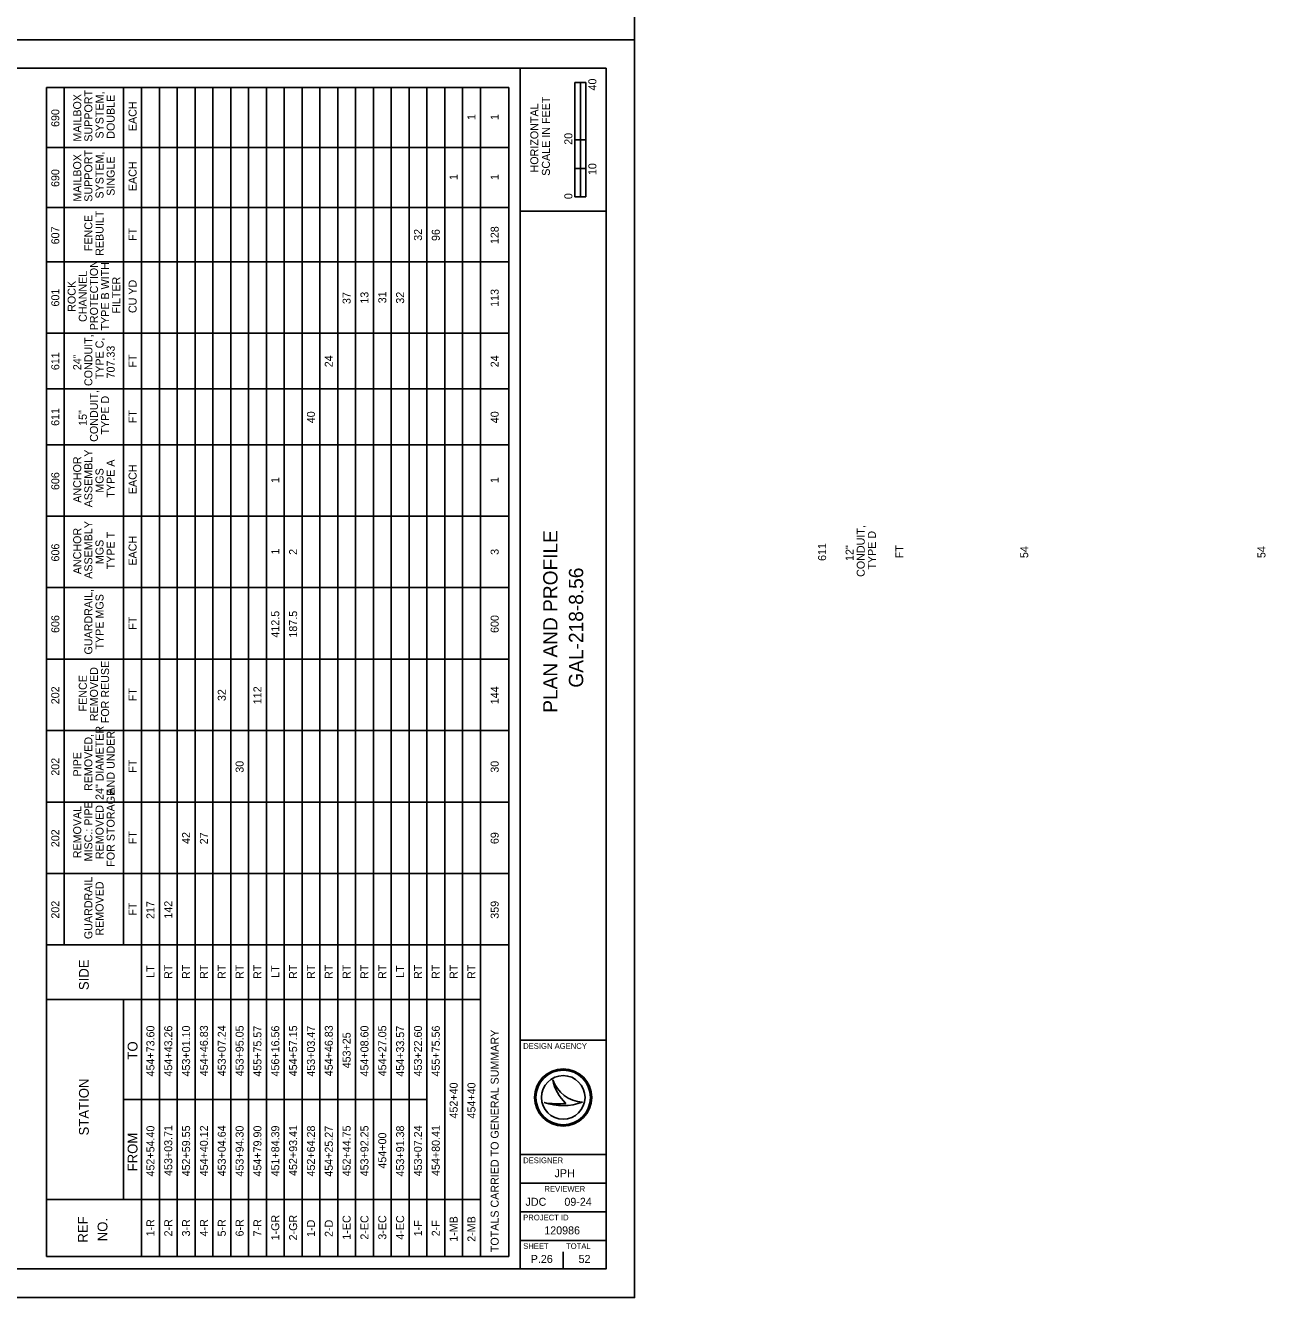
# Model space of a CAD drawing. Extents: x 0 to 3369, y -440 to 440.
# Drawn here: x 466.9 to 900.7, y -440 to 5 of the extents above; entities that cross this region are included whole.
import ezdxf

# ---------------------------------------------------------------- set-up
doc = ezdxf.new("R2010")
doc.units = 0
for name, color, linetype in [('DR_X_Culvert', 7, 'Continuous'), ('PF_X_Ground_Line', 7, 'Continuous'), ('PV_P_EOP', 7, 'Continuous'), ('SC_Scratch1', 7, 'Continuous')]:
    doc.layers.add(name, color=color, linetype=linetype)

msp = doc.modelspace()

# ---------------------------------------------------------------- linework, layer by layer
at = {"layer": 'DR_X_Culvert'}
for p, q in [((474.19, -16.67), (474.19, -425.68)), ((636.03, -16.67), (474.19, -16.67)), ((480.43, -16.67), (480.43, -316.67)), ((501.23, -16.67), (501.23, -316.67)), ((507.47, -16.67), (507.47, -425.68)), ((513.71, -16.67), (513.71, -425.68)), ((519.95, -16.67), (519.95, -425.68)), ((526.19, -16.67), (526.19, -425.68)), ((532.43, -16.67), (532.43, -425.68)), ((538.67, -16.67), (538.67, -425.68)), ((544.91, -16.67), (544.91, -425.68)), ((551.15, -16.67), (551.15, -425.68)), ((557.39, -16.67), (557.39, -425.68)), ((563.63, -16.67), (563.63, -425.68)), ((569.87, -16.67), (569.87, -425.68)), ((576.11, -16.67), (576.11, -425.68)), ((582.35, -16.67), (582.35, -425.68)), ((588.59, -16.67), (588.59, -425.68)), ((594.83, -16.67), (594.83, -425.68)), ((601.07, -16.67), (601.07, -425.68)), ((607.31, -16.67), (607.31, -425.68)), ((613.55, -16.67), (613.55, -425.68)), ((619.79, -16.67), (619.79, -425.68)), ((626.03, -16.67), (626.03, -425.68)), ((636.03, -16.67), (636.03, -425.68)), ((659.13, -55), (659.13, -15)), ((662.88, -15), (659.13, -15)), ((659.13, -35), (659.13, -15)), ((659.13, -15), (661, -15)), ((661, -15), (661.02, -15)), ((661.02, -15), (661.02, -35)), ((662.88, -15), (662.88, -55)), ((661.02, -35), (659.13, -35)), ((662.87, -35), (661, -35)), ((661, -35), (661, -45)), ((662.87, -45), (662.87, -35)), ((636.03, -37.67), (474.19, -37.67)), ((661, -45), (659.13, -45)), ((659.13, -45), (659.13, -55)), ((661, -55), (661, -45)), ((661, -45), (662.87, -45)), ((662.88, -55), (659.13, -55)), ((659.13, -55), (661, -55)), ((636.03, -58.67), (474.19, -58.67)), ((636.03, -77.67), (474.19, -77.67)), ((636.03, -102.67), (474.19, -102.67)), ((636.03, -122.17), (474.19, -122.17)), ((636.03, -141.67), (474.19, -141.67)), ((636.03, -166.67), (474.19, -166.67)), ((636.03, -191.67), (474.19, -191.67)), ((636.03, -216.67), (474.19, -216.67)), ((636.03, -241.67), (474.19, -241.67)), ((636.03, -266.67), (474.19, -266.67)), ((636.03, -291.67), (474.19, -291.67)), ((636.03, -316.67), (474.19, -316.67)), ((474.19, -335.68), (626.03, -335.68)), ((501.23, -335.68), (501.23, -405.68)), ((651.35, -363.81), (651.35, -363.81)), ((501.23, -370.68), (607.31, -370.68)), ((648.34, -371.81), (648.34, -371.81)), ((655, -370), (655, -370)), ((661.75, -371.63), (661.75, -371.63)), ((474.19, -405.68), (626.03, -405.68)), ((474.19, -425.68), (636.03, -425.68)), ((647.5, -426.5), (647.5, -426.5)), ((655, -430), (655, -424))]:
    msp.add_line(p, q, dxfattribs=at)
for radius in [10, 9.54, 9.54, 7.64]:
    msp.add_circle((655, -370), radius, dxfattribs=at)
for centre, radius, start, end in [((662.32, -360.05), 11.6, 198.9257, 198.9319), ((666.93, -360.6), 15.91, 191.6379, 191.6421), ((662.32, -360.05), 11.6, 198.9319, 267.1657), ((666.93, -360.6), 15.91, 191.6421, 226.0947), ((654.79, -352.6), 20.26, 251.4576, 290.0832), ((652.96, -346.91), 25.32, 259.4964, 259.4995), ((654.79, -352.6), 20.26, 251.4527, 251.4576), ((652.96, -346.91), 25.32, 259.4995, 276.6672)]:
    msp.add_arc(centre, radius, start, end, dxfattribs=at)
at = {"layer": 'PF_X_Ground_Line'}
for p, q in [((640, -430), (640, -10)), ((640, -60), (670, -60)), ((640, -350), (670, -350)), ((640, -390), (670, -390)), ((640, -400), (670, -400)), ((640, -410), (670, -410)), ((640, -420), (670, -420))]:
    msp.add_line(p, q, dxfattribs=at)
msp.add_lwpolyline([(30, -10), (670, -10), (670, -430), (30, -430)], close=True, dxfattribs=at)
at = {"layer": 'SC_Scratch1'}
for points in [[(0, 0), (680, 0), (680, 440), (0, 440)], [(0, -440), (680, -440), (680, 0), (0, 0)]]:
    msp.add_lwpolyline(points, close=True, dxfattribs=at)

# ---------------------------------------------------------------- texts
at = {"layer": 'DR_X_Culvert'}
for s, height, p in [('40', 2.8, (666.61, -17.75)), ('SCALE IN FEET', 2.8, (650.35, -47.59)), ('HORIZONTAL', 2.8, (646.3, -46.42)), ('20', 2.8, (658.21, -36.75)), ('10', 2.8, (666.61, -47.35)), ('0', 2.8, (658.21, -55.77)), ('PLAN AND PROFILE', 5, (653, -235.45)), ('GAL-218-8.56', 5, (662, -226.65)), ('SIDE', 3.435, (489.03, -332.45)), ('TOTALS CARRIED TO GENERAL SUMMARY', 2.8, (632.43, -424.12)), ('TO', 3.435, (506.07, -356.75)), ('STATION', 3.435, (489.03, -383.29)), ('FROM', 3.435, (506.07, -395.85)), ('REF', 3.436, (488.68, -420.78)), ('NO.', 3.436, (495.55, -420.31))]:
    msp.add_text(s, height=height, rotation=90, dxfattribs=at).set_placement(p)
for s, height, p in [('DESIGN AGENCY', 2, (641, -353)), ('DESIGNER', 2, (641, -393)), ('JPH', 2.8, (651.97, -397.9)), ('REVIEWER', 2, (648.44, -403)), ('JDC', 2.8, (641.82, -407.9)), ('09-24', 2.8, (655.42, -407.9)), ('PROJECT ID', 2, (641, -413)), ('120986', 2.8, (648.38, -417.9)), ('SHEET', 2, (641, -423)), ('TOTAL', 2, (656, -423)), ('P.26', 2.8, (643.65, -427.9)), ('52', 2.8, (660.39, -427.9))]:
    msp.add_text(s, height=height, dxfattribs=at).set_placement(p)
at = {"layer": 'PV_P_EOP'}
for s, p in [('SUPPORT', (490.28, -35.67)), ('MAILBOX', (486.38, -35.64)), ('SYSTEM,', (494.18, -34.55)), ('DOUBLE', (498.08, -34.63)), ('EACH', (505.75, -31.96)), ('690', (478.71, -30.51)), ('1', (624.31, -28.08)), ('1', (632.43, -28.08)), ('SUPPORT', (490.28, -56.67)), ('SYSTEM,', (494.18, -55.55)), ('MAILBOX', (486.38, -56.64)), ('SINGLE', (498.08, -54.58)), ('EACH', (505.75, -52.96)), ('690', (478.71, -51.51)), ('1', (618.07, -49.08)), ('1', (632.43, -49.08)), ('FENCE', (490.28, -73.95)), ('REBUILT', (494.18, -75.6)), ('607', (478.71, -71.58)), ('FT', (505.75, -70.41)), ('32', (605.59, -70.33)), ('96', (611.83, -70.41)), ('128', (632.43, -71.5)), ('PROTECTION', (492.23, -101.64)), ('TYPE B WITH', (496.13, -101.69)), ('ROCK', (484.43, -95.18)), ('CHANNEL', (488.33, -98.72)), ('FILTER', (500.04, -95.79)), ('CU YD', (505.75, -95.62)), ('601', (478.71, -93.32)), ('37', (580.63, -92.47)), ('13', (586.87, -92.32)), ('31', (593.11, -92.2)), ('32', (599.35, -92.33)), ('113', (632.43, -93.44)), ('CONDUIT,', (490.28, -121.15)), ('TYPE C,', (494.18, -118.77)), ('611', (478.71, -115.57)), ('24"', (486.38, -115.57)), ('707.33', (498.08, -118.48)), ('FT', (505.75, -114.66)), ('24', (574.39, -114.57)), ('24', (632.43, -114.57)), ('CONDUIT,', (492.23, -140.65)), ('611', (478.71, -135.07)), ('TYPE D', (496.13, -138.1)), ('15"', (488.33, -135.07)), ('FT', (505.75, -134.16)), ('40', (568.15, -134.15)), ('40', (632.43, -134.15)), ('ANCHOR', (486.38, -161.98)), ('ASSEMBLY', (490.28, -163.57)), ('MGS', (494.18, -158.44)), ('TYPE A', (498.08, -160.18)), ('EACH', (505.75, -158.96)), ('606', (478.71, -157.52)), ('1', (555.67, -155.08)), ('1', (632.43, -155.08)), ('ASSEMBLY', (490.28, -188.57)), ('ANCHOR', (486.38, -186.98)), ('TYPE T', (498.08, -185.26)), ('CONDUIT,', (760.49, -187.9)), ('TYPE D', (764.39, -185.35)), ('606', (478.71, -182.52)), ('MGS', (494.18, -183.44)), ('EACH', (505.75, -183.96)), ('611', (746.97, -182.32)), ('12"', (756.59, -182.32)), ('FT', (774.01, -181.41)), ('54', (817.69, -181.32)), ('54', (900.69, -181.32)), ('1', (555.67, -180.08)), ('2', (561.91, -180.21)), ('3', (632.43, -180.2)), ('GUARDRAIL,', (490.28, -215.05)), ('TYPE MGS', (494.18, -213.3)), ('412.5', (555.67, -209.15)), ('187.5', (561.91, -209.15)), ('606', (478.71, -207.52)), ('FT', (505.75, -206.41)), ('600', (632.43, -207.51)), ('FOR REUSE', (496.13, -239.1)), ('FENCE', (488.33, -234.95)), ('REMOVED', (492.23, -238.39)), ('202', (478.71, -232.45)), ('FT', (505.75, -231.41)), ('112', (549.43, -232.45)), ('144', (632.43, -232.44)), ('32', (536.95, -231.33)), ('24" DIAMETER', (494.18, -265.92)), ('REMOVED,', (490.28, -262.8)), ('AND UNDER', (498.08, -264.04)), ('202', (478.71, -257.45)), ('PIPE', (486.38, -257.72)), ('FT', (505.75, -256.41)), ('30', (543.19, -256.4)), ('30', (632.43, -256.4)), ('FOR STORAGE', (498.08, -289.3)), ('MISC.: PIPE', (490.28, -287.42)), ('REMOVAL', (486.38, -286.32)), ('REMOVED', (494.18, -286.63)), ('202', (478.71, -282.45)), ('FT', (505.75, -281.41)), ('42', (524.47, -281.33)), ('27', (530.71, -281.47)), ('69', (632.43, -281.37)), ('GUARDRAIL', (490.28, -314.61)), ('REMOVED', (494.18, -313.39)), ('202', (478.71, -307.45)), ('FT', (505.75, -306.41)), ('217', (511.99, -307.58)), ('142', (518.23, -307.45)), ('359', (632.43, -307.49)), ('LT', (511.99, -328.16)), ('RT', (518.23, -328.55)), ('RT', (524.47, -328.55)), ('RT', (530.71, -328.55)), ('RT', (536.95, -328.55)), ('RT', (543.19, -328.55)), ('RT', (549.43, -328.55)), ('LT', (555.67, -328.16)), ('RT', (561.91, -328.55)), ('RT', (568.15, -328.55)), ('RT', (574.39, -328.55)), ('RT', (580.63, -328.55)), ('RT', (586.87, -328.55)), ('RT', (593.11, -328.55)), ('LT', (599.35, -328.16)), ('RT', (605.59, -328.55)), ('RT', (611.83, -328.55)), ('RT', (618.07, -328.55)), ('RT', (624.31, -328.55)), ('454+73.60', (511.99, -362.66)), ('454+43.26', (518.23, -362.67)), ('453+01.10', (524.47, -362.66)), ('454+46.83', (530.71, -362.58)), ('453+07.24', (536.95, -362.58)), ('453+95.05', (543.19, -362.61)), ('455+75.57', (549.43, -362.73)), ('456+16.56', (555.67, -362.67)), ('454+57.15', (561.91, -362.61)), ('453+03.47', (568.15, -362.73)), ('454+46.83', (574.39, -362.58)), ('454+08.60', (586.87, -362.66)), ('454+27.05', (593.11, -362.61)), ('454+33.57', (599.35, -362.73)), ('453+22.60', (605.59, -362.66)), ('455+75.56', (611.83, -362.67)), ('453+25', (580.63, -359.82)), ('452+40', (618.07, -377.36)), ('454+40', (624.31, -377.36)), ('452+54.40', (511.99, -397.66)), ('453+03.71', (518.23, -397.46)), ('452+59.55', (524.47, -397.61)), ('454+40.12', (530.71, -397.59)), ('453+04.64', (536.95, -397.58)), ('453+94.30', (543.19, -397.66)), ('454+79.90', (549.43, -397.66)), ('451+84.39', (555.67, -397.63)), ('452+93.41', (561.91, -397.46)), ('452+64.28', (568.15, -397.64)), ('454+25.27', (574.39, -397.73)), ('452+44.75', (580.63, -397.61)), ('453+92.25', (586.87, -397.61)), ('454+00', (593.11, -394.88)), ('453+91.38', (599.35, -397.64)), ('453+07.24', (605.59, -397.6)), ('454+80.41', (611.83, -397.48)), ('1-R', (511.99, -418.62)), ('2-R', (518.23, -418.62)), ('3-R', (524.47, -418.62)), ('4-R', (530.71, -418.62)), ('5-R', (536.95, -418.62)), ('6-R', (543.19, -418.62)), ('7-R', (549.43, -418.62)), ('1-GR', (555.67, -420.01)), ('2-GR', (561.91, -420.01)), ('1-D', (568.15, -418.79)), ('2-D', (574.39, -418.79)), ('1-EC', (580.63, -419.75)), ('2-EC', (586.87, -419.75)), ('3-EC', (593.11, -419.75)), ('4-EC', (599.35, -419.75)), ('1-F', (605.59, -418.56)), ('2-F', (611.83, -418.56)), ('1-MB', (618.07, -420.49)), ('2-MB', (624.31, -420.49))]:
    msp.add_text(s, height=2.8, rotation=90, dxfattribs=at).set_placement(p)

doc.saveas('drawing.dxf')
